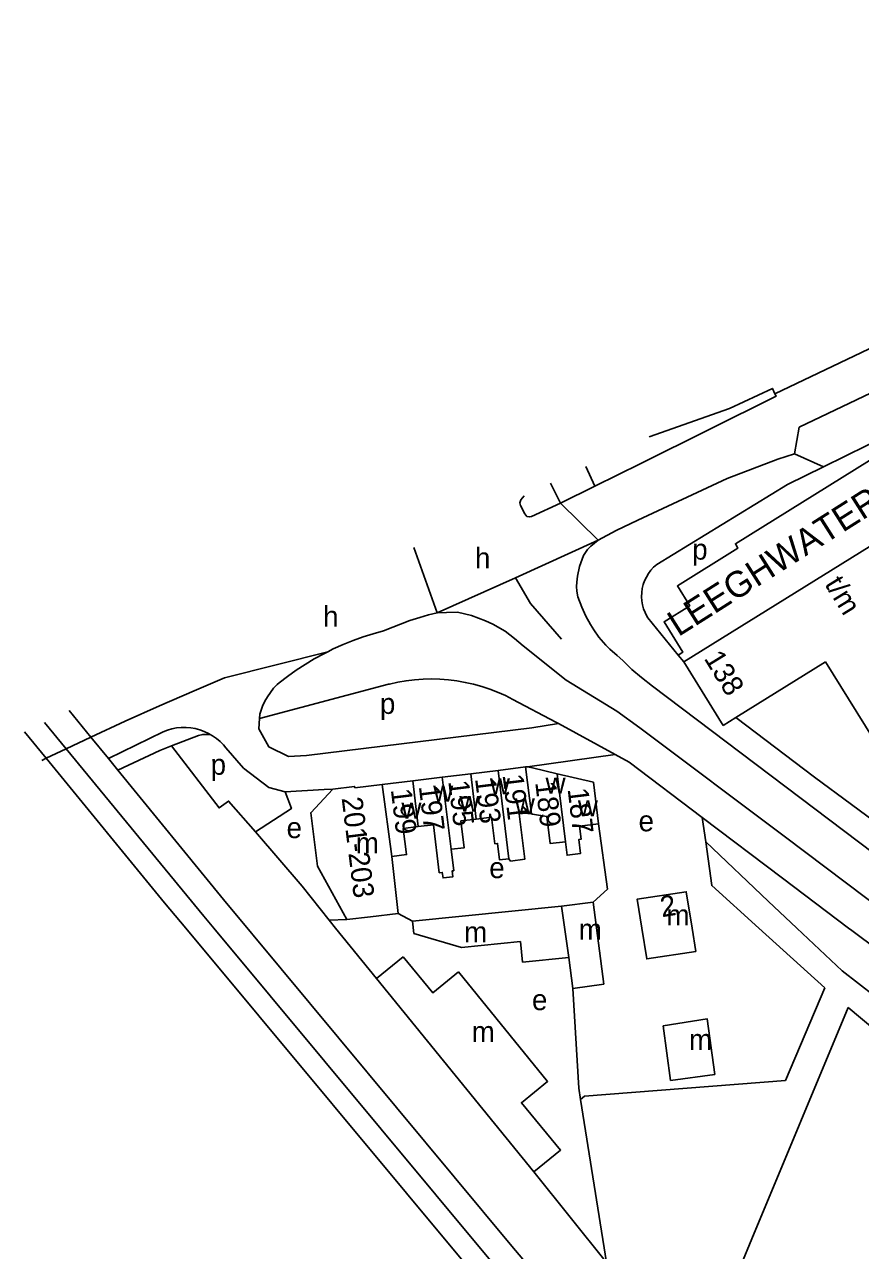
# Model space of a CAD drawing. Extents: x 159902 to 161769, y 383692 to 384875.
# Drawn here: x 159902 to 160063.3, y 384437.8 to 384674.3 of the extents above; entities that cross this region are included whole.
import ezdxf

# ---------------------------------------------------------------- set-up
doc = ezdxf.new("R2010")
doc.units = 0
for name, color, linetype in [('BLT_Basislijn', 7, 'Continuous'), ('BLT_Bebouwing', 7, 'Continuous'), ('BLT_Centroide', 7, 'Continuous'), ('BLT_Huisnummer', 7, 'Continuous'), ('BLT_Huisnummer_ tussenligend', 7, 'Continuous'), ('BLT_Huisnummer_reeks', 7, 'Continuous'), ('BLT_Onderverdeling_panden', 7, 'Continuous'), ('BLT_Spoorlijn', 7, 'Continuous'), ('BLT_Straatnaam', 7, 'Continuous'), ('BLT_Vlakafsluiter', 7, 'Continuous')]:
    doc.layers.add(name, color=color, linetype=linetype)

msp = doc.modelspace()

# ---------------------------------------------------------------- linework, layer by layer
at = {"layer": 'BLT_Basislijn'}
for p, q in [((160079.75, 384600.65), (160056.1, 384589.01)), ((160050.54, 384591.52), (160056.1, 384589.01)), ((160010.28, 384589.03), (160012.02, 384585.26)), ((160003.49, 384585.83), (160005.39, 384582.01)), ((160022.25, 384559.89), (160028.1, 384552.68)), ((160028.1, 384552.68), (160029.18, 384551.35)), ((160021.05, 384548.37), (160023.14, 384546.71)), ((159972.23, 384547.05), (159947.36, 384540.46)), ((160084.82, 384500), (160023.14, 384546.71)), ((159996.24, 384544.11), (160004.51, 384539.76)), ((159910.66, 384541.99), (159914.83, 384536.86)), ((159947.41, 384541.26), (159947.36, 384540.46)), ((160004.51, 384539.76), (160005.04, 384539.46)), ((160005.04, 384539.46), (160015.96, 384533.51)), ((160054.4, 384529.13), (160039.23, 384540.61)), ((159914.83, 384536.86), (159918.2, 384532.73)), ((159928.74, 384537.9), (159918.2, 384532.73)), ((159930.38, 384535.2), (159935.56, 384537.19)), ((159918.2, 384532.73), (159920.02, 384530.49)), ((159999.01, 384531.13), (160015.96, 384533.51)), ((160015.96, 384533.51), (160018.64, 384532.05)), ((160032.75, 384521.36), (160018.64, 384532.05)), ((159920.02, 384530.49), (159940.43, 384505.52)), ((160093.76, 384500), (160054.4, 384529.13)), ((159961.49, 384526.83), (159959.81, 384526.73)), ((160012.76, 384520.14), (160014.5, 384507.49)), ((160048.2, 384509.67), (160032.75, 384521.36)), ((159955.56, 384508.1), (159946.56, 384518.57)), ((159960.79, 384501.52), (159955.56, 384508.1)), ((160060.98, 384500), (160048.2, 384509.67)), ((160011.68, 384505.01), (160014.5, 384507.49)), ((159940.43, 384505.52), (159996.04, 384438.67)), ((159960.79, 384501.52), (159964.18, 384501.69)), ((159962, 384500), (159960.79, 384501.52)), ((159969.94, 384490.3), (159962, 384500)), ((160043.66, 384500), (160056.38, 384488.5)), ((160008.95, 384469.12), (160007.8, 384488.36)), ((160066.01, 384480.41), (160060.87, 384484.72)), ((160009.26, 384466.95), (160008.95, 384469.12)), ((160009.26, 384466.95), (160014.3, 384435.51)), ((159996.04, 384438.67), (160054.95, 384368.53))]:
    msp.add_line(p, q, dxfattribs=at)
for points in [[(160046.76, 384603.09), (160071.81, 384615.04), (160118.96, 384637.58), (160196.63, 384674.33)], [(160051.44, 384596.66), (160115.06, 384627), (160159.61, 384647.8)], [(160046.76, 384603.09), (160047, 384602.62), (160020.88, 384589.65), (160012.02, 384585.26)], [(160022.5, 384594.78), (160037.99, 384600.23), (160046.28, 384604.13), (160046.76, 384603.09)], [(160080.31, 384599.75), (160039.13, 384574.15), (160039.62, 384573.31), (160027.94, 384566.02), (160030.32, 384562.19), (160025.38, 384559.12), (160029.03, 384553.26), (160028.1, 384552.68)], [(160016.12, 384576.7), (160020.33, 384578.73), (160037.52, 384586.75), (160047.31, 384590.47), (160050.54, 384591.52)], [(160056.1, 384589.01), (160049.18, 384585.6), (160023.96, 384570.14)], [(160012.02, 384585.26), (160005.39, 384582.01)], [(160005.39, 384582.01), (159999.82, 384579.43), (159999.4, 384579.33), (159998.94, 384579.44), (159998.51, 384579.92), (159997.71, 384581.51), (159997.59, 384582.04), (159997.77, 384582.63), (159998.38, 384583.43)], [(160016.12, 384576.7), (160012.66, 384574.85)], [(160012.66, 384574.85), (160011.24, 384573.72), (160010.59, 384573.03), (160009.85, 384571.92), (160009.57, 384571.21), (160009.08, 384569.79), (160008.71, 384567.88), (160008.53, 384566.74), (160008.5, 384565.92), (160008.53, 384565.04), (160008.72, 384563.93), (160009.53, 384561.95), (160010.28, 384560.17)], [(160023.96, 384570.14), (160023.37, 384569.62), (160022.84, 384569.04), (160022.36, 384568.41), (160021.96, 384567.73), (160021.62, 384567.02), (160021.36, 384566.27), (160021.17, 384565.51), (160021.07, 384564.73), (160021.04, 384563.94), (160021.09, 384563.15), (160021.22, 384562.37), (160021.43, 384561.61), (160021.72, 384560.88), (160022.08, 384560.18), (160022.25, 384559.89)], [(159996.75, 384567.55), (159999.61, 384562.64), (160005.58, 384555.75)], [(159971.27, 384557.35), (159976.37, 384559.38), (159978.26, 384559.95), (159979.92, 384560.45), (159981.61, 384560.83)], [(159981.61, 384560.83), (159983.4, 384560.91), (159985.56, 384560.93), (159988.24, 384560.32), (159990.94, 384559.27), (159992.38, 384558.65), (159994.76, 384557.3), (159996.54, 384555.86), (159998.2, 384554.45)], [(160010.28, 384560.17), (160011.21, 384558.59), (160011.85, 384557.52), (160012.82, 384556.15), (160014.16, 384554.6), (160014.95, 384553.85), (160016.34, 384552.62), (160017.4, 384551.61), (160019.15, 384549.88), (160021.05, 384548.37)], [(159971.27, 384557.35), (159969.29, 384556.81), (159967.32, 384556.18), (159965.38, 384555.48), (159963.46, 384554.71), (159961.58, 384553.86), (159960.5, 384553.32)], [(159960.5, 384553.32), (159959.73, 384552.93), (159957.92, 384551.94), (159956.15, 384550.88), (159954.42, 384549.75), (159952.74, 384548.56), (159951.11, 384547.3), (159950.76, 384547.02)], [(159998.2, 384554.45), (160006.47, 384547.85), (160016.29, 384541.83), (160020.7, 384538.66), (160048.79, 384517.58), (160072.06, 384500)], [(159914.83, 384536.86), (159921.43, 384539.92), (159928.06, 384542.9), (159934.72, 384545.81), (159940.57, 384548.29)], [(159950.76, 384547.02), (159950.07, 384546.28), (159949.44, 384545.48), (159948.87, 384544.64), (159948.38, 384543.76), (159947.95, 384542.84), (159947.6, 384541.89), (159947.41, 384541.26)], [(159996.24, 384544.11), (159994.78, 384544.85), (159993.28, 384545.51), (159991.76, 384546.1), (159990.2, 384546.62), (159988.63, 384547.06), (159987.03, 384547.42), (159985.42, 384547.7), (159983.79, 384547.9), (159982.16, 384548.03), (159980.52, 384548.07), (159978.89, 384548.03), (159977.26, 384547.92), (159975.63, 384547.72), (159974.02, 384547.45), (159972.42, 384547.09), (159972.23, 384547.05)], [(159947.36, 384540.46), (159947.21, 384538.43), (159949.12, 384534.99), (159952.94, 384533.1), (159956.4, 384533.31), (159999.85, 384538.66), (160005.04, 384539.46)], [(159928.74, 384537.9), (159929.59, 384538.22), (159930.46, 384538.46), (159931.36, 384538.62), (159932.26, 384538.71), (159933.17, 384538.72), (159934.07, 384538.64), (159934.96, 384538.49), (159935.84, 384538.25), (159936.7, 384537.94), (159937.52, 384537.56), (159937.86, 384537.36)], [(159935.56, 384537.19), (159936.39, 384537.38), (159937.86, 384537.36)], [(159937.86, 384537.36), (159938.3, 384537.11), (159939.05, 384536.59), (159939.74, 384536), (159940.38, 384535.36), (159940.85, 384534.8)], [(159930.38, 384535.2), (159928.13, 384534.26), (159920.02, 384530.49)], [(159946.56, 384518.57), (159941.38, 384524.5), (159939.54, 384523.21), (159930.38, 384535.2)], [(159952.27, 384526.29), (159949.17, 384527.11), (159944.29, 384530.88), (159940.85, 384534.8)], [(159946.56, 384518.57), (159953.49, 384523.07), (159952.27, 384526.29)], [(159959.81, 384526.73), (159952.27, 384526.29)], [(160032.75, 384521.36), (160033.41, 384516.64)], [(160033.41, 384516.64), (160045.43, 384505.19), (160050.98, 384500)], [(160033.41, 384516.64), (160034.59, 384508.21), (160043.66, 384500)], [(159976.84, 384501.32), (159974.11, 384502.83)], [(160050.98, 384500), (160059.76, 384491.77), (160066.06, 384486.87)], [(160097.39, 384472.82), (160061.59, 384499.54), (160060.98, 384500)], [(160056.38, 384488.5), (160048.8, 384470.6)], [(160042.31, 384440.06), (160060.87, 384484.72)], [(160048.8, 384470.6), (160010.02, 384467.58), (160009.26, 384466.95)], [(160014.3, 384435.51), (160000.25, 384452.97)], [(160080.27, 384410.34), (160070.65, 384413.88), (160073.45, 384421.36), (160040.16, 384434.89), (160042.31, 384440.06)]]:
    msp.add_lwpolyline(points, dxfattribs=at)
at = {"layer": 'BLT_Bebouwing'}
for p, q in [((160029.18, 384551.35), (160087.76, 384587.81)), ((160036.78, 384539.12), (160029.18, 384551.35)), ((160039.23, 384540.61), (160056.49, 384551.38)), ((160082.79, 384509.05), (160056.49, 384551.38)), ((160036.78, 384539.12), (160039.23, 384540.61)), ((159982.59, 384529.11), (159988.09, 384529.79)), ((159988.09, 384529.79), (159993.36, 384530.43)), ((159993.36, 384530.43), (159998.67, 384531.09)), ((159998.67, 384531.09), (159999.01, 384531.13)), ((159999.01, 384531.13), (160000, 384530.9)), ((160000, 384530.9), (160004.74, 384529.79)), ((160004.74, 384529.79), (160011.77, 384528.15)), ((159965.71, 384527.04), (159971.03, 384527.69)), ((159971.03, 384527.69), (159976.9, 384528.41)), ((159976.9, 384528.41), (159982.59, 384529.11)), ((160012.76, 384520.14), (160011.77, 384528.15)), ((160000, 384522), (159999.78, 384522.03)), ((159972.84, 384513.85), (159974.11, 384502.83)), ((159976.84, 384501.32), (160005.61, 384504.26)), ((160005.61, 384504.26), (160011.68, 384505.01)), ((160011.68, 384505.01), (160013.74, 384489.17)), ((159968.76, 384502.18), (159964.18, 384501.69)), ((159974.11, 384502.83), (159968.76, 384502.18)), ((159977.13, 384498.94), (159976.84, 384501.32)), ((159986.33, 384496.28), (159977.13, 384498.94)), ((159997.66, 384497.43), (159986.33, 384496.28)), ((159998.08, 384493.44), (159997.66, 384497.43)), ((159975.08, 384494.48), (159969.94, 384490.3)), ((160006.98, 384494.35), (159998.08, 384493.44)), ((160007.8, 384488.36), (160006.98, 384494.35)), ((160000.25, 384452.97), (159969.94, 384490.3)), ((160013.74, 384489.17), (160007.8, 384488.36))]:
    msp.add_line(p, q, dxfattribs=at)
for points in [[(159961.49, 384526.83), (159965.67, 384527.34), (159965.71, 384527.04)], [(159964.18, 384501.69), (159958.51, 384511.94), (159957.91, 384517.12), (159957.24, 384522.25), (159961.49, 384526.83)], [(159984.3, 384515.21), (159984.8, 384511.06), (159984.5, 384511.05), (159984.64, 384509.93), (159982.74, 384509.69), (159982.61, 384510.75), (159982.03, 384510.68), (159980.89, 384519.96), (159977.98, 384519.6)], [(159989.16, 384521.04), (159986.21, 384520.68), (159986.85, 384515.52), (159984.3, 384515.21)], [(159995.46, 384513.37), (159993.65, 384513.15), (159993.26, 384516.34), (159992.74, 384516.28), (159992.12, 384521.4), (159989.16, 384521.04)], [(159999.78, 384522.03), (159998.8, 384522.2), (159997.43, 384522.03), (159998.5, 384513.28), (159995.79, 384512.94), (159995.46, 384513.37)], [(160000, 384522), (160002.77, 384521.54), (160003.42, 384516.32), (160006.36, 384516.68)], [(160006.36, 384516.68), (160006.68, 384514.07), (160009.26, 384514.39), (160008.92, 384517.1), (160009.36, 384517.15), (160009.05, 384519.68), (160012.76, 384520.14)], [(159977.98, 384519.6), (159975.08, 384519.24), (159975.7, 384514.2), (159972.84, 384513.85)], [(160021.08, 384500), (160020.19, 384505.58), (160029.65, 384507.03), (160030.78, 384500)], [(160021.08, 384500), (160022.03, 384494.05), (160031.49, 384495.51), (160030.78, 384500)], [(159985.73, 384491.55), (159980.76, 384487.52), (159975.08, 384494.48)], [(159985.73, 384491.55), (160002.91, 384470.43), (159997.87, 384466.33), (160005.41, 384457.17), (160000.25, 384452.97)], [(160025.22, 384481.13), (160026.64, 384470.63), (160035.16, 384471.78), (160033.7, 384482.48), (160025.22, 384481.13)]]:
    msp.add_lwpolyline(points, dxfattribs=at)
at = {"layer": 'BLT_Onderverdeling_panden'}
for p, q in [((159989.16, 384521.04), (159988.09, 384529.79)), ((159995.46, 384513.37), (159993.36, 384530.43)), ((159999.78, 384522.03), (159998.67, 384531.09)), ((160006.36, 384516.68), (160004.74, 384529.79)), ((159972.84, 384513.85), (159971.03, 384527.69)), ((159977.98, 384519.6), (159976.9, 384528.41)), ((159984.3, 384515.21), (159982.59, 384529.11)), ((160006.98, 384494.35), (160005.61, 384504.26))]:
    msp.add_line(p, q, dxfattribs=at)
at = {"layer": 'BLT_Spoorlijn'}
for p, q in [((159905.86, 384539.7), (159910.05, 384534.6)), ((159902.02, 384537.87), (159906.2, 384532.78)), ((159910.05, 384534.6), (159936.59, 384502.32)), ((159906.2, 384532.78), (159929.04, 384504.9))]:
    msp.add_line(p, q, dxfattribs=at)
for points in [[(159929.04, 384504.9), (159933.12, 384500)], [(159936.59, 384502.32), (159938.52, 384500)], [(159933.12, 384500), (159989.81, 384431.98)], [(159938.52, 384500), (159992.2, 384435.47)]]:
    msp.add_lwpolyline(points, dxfattribs=at)
at = {"layer": 'BLT_Vlakafsluiter'}
for p, q in [((160051.44, 384596.66), (160050.54, 384591.52)), ((160005.39, 384582.01), (160012.66, 384574.85)), ((160012.66, 384574.85), (159996.75, 384567.55)), ((159981.61, 384560.83), (159977.11, 384573.42)), ((159996.75, 384567.55), (159981.61, 384560.83)), ((159960.5, 384553.32), (159940.57, 384548.29)), ((159914.83, 384536.86), (159910.05, 384534.6)), ((159910.05, 384534.6), (159906.2, 384532.78)), ((159906.2, 384532.78), (159905.34, 384532.37))]:
    msp.add_line(p, q, dxfattribs=at)

# ---------------------------------------------------------------- texts
at = {"layer": 'BLT_Centroide'}
for s, p in [('h', (159988.91, 384569.4)), ('h', (159959.61, 384558.13)), ('p', (159970.57, 384541.33)), ('p', (159937.92, 384529.58)), ('w', (159980.84, 384524.42)), ('w', (159991.78, 384525.81)), ('w', (160002.52, 384525.95)), ('w', (159985.88, 384522.45)), ('w', (159996.58, 384521.94)), ('w', (160008.75, 384521.59)), ('w', (159974.72, 384521.12)), ('e', (159952.57, 384517.37)), ('e', (160020.46, 384518.68)), ('m', (159965.91, 384514.45)), ('e', (159991.66, 384509.65)), ('m', (160025.84, 384500.53)), ('m', (159986.81, 384497.25)), ('m', (160008.92, 384497.78)), ('e', (159999.9, 384484.18)), ('m', (159988.27, 384478.03)), ('m', (160030.19, 384476.5))]:
    msp.add_text(s, height=4, dxfattribs=at).set_placement(p)
msp.add_text('p', height=4, rotation=359, dxfattribs=at).set_placement((160030.78, 384571.12))
at = {"layer": 'BLT_Huisnummer'}
for s, rotation, p in [('191', 277.0134, (159994.22, 384529.53)), ('195', 277.0129, (159983.74, 384528.34)), ('199', 277.002, (159972.66, 384526.73)), ('187', 277.012, (160006.76, 384526.84)), ('2', 9.0707, (160024.96, 384502.1))]:
    msp.add_text(s, height=4, rotation=rotation, dxfattribs=at).set_placement(p)
at = {"layer": 'BLT_Huisnummer_ tussenligend'}
for s, rotation, p in [('197', 277.0129, (159978.06, 384527.36)), ('193', 277.0134, (159988.91, 384528.83)), ('189', 277.012, (160000.51, 384528.11))]:
    msp.add_text(s, height=4, rotation=rotation, dxfattribs=at).set_placement(p)
at = {"layer": 'BLT_Huisnummer_reeks'}
for s, rotation, p in [('t/m', 301.4944, (160056.25, 384566.38)), ('138', 301.4944, (160032.98, 384552.05)), ('201-203', 277.0051, (159963.18, 384525.1))]:
    msp.add_text(s, height=4, rotation=rotation, dxfattribs=at).set_placement(p)
at = {"layer": 'BLT_Straatnaam'}
msp.add_text('LEEGHWATERSTRAAT', height=5, rotation=32.3945, dxfattribs=at).set_placement((160028.14, 384556.13))

doc.saveas('drawing.dxf')
